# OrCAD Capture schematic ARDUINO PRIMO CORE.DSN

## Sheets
1 Revision: title: Title and Reversion History; note: FM03-AR9331-DogWiFi
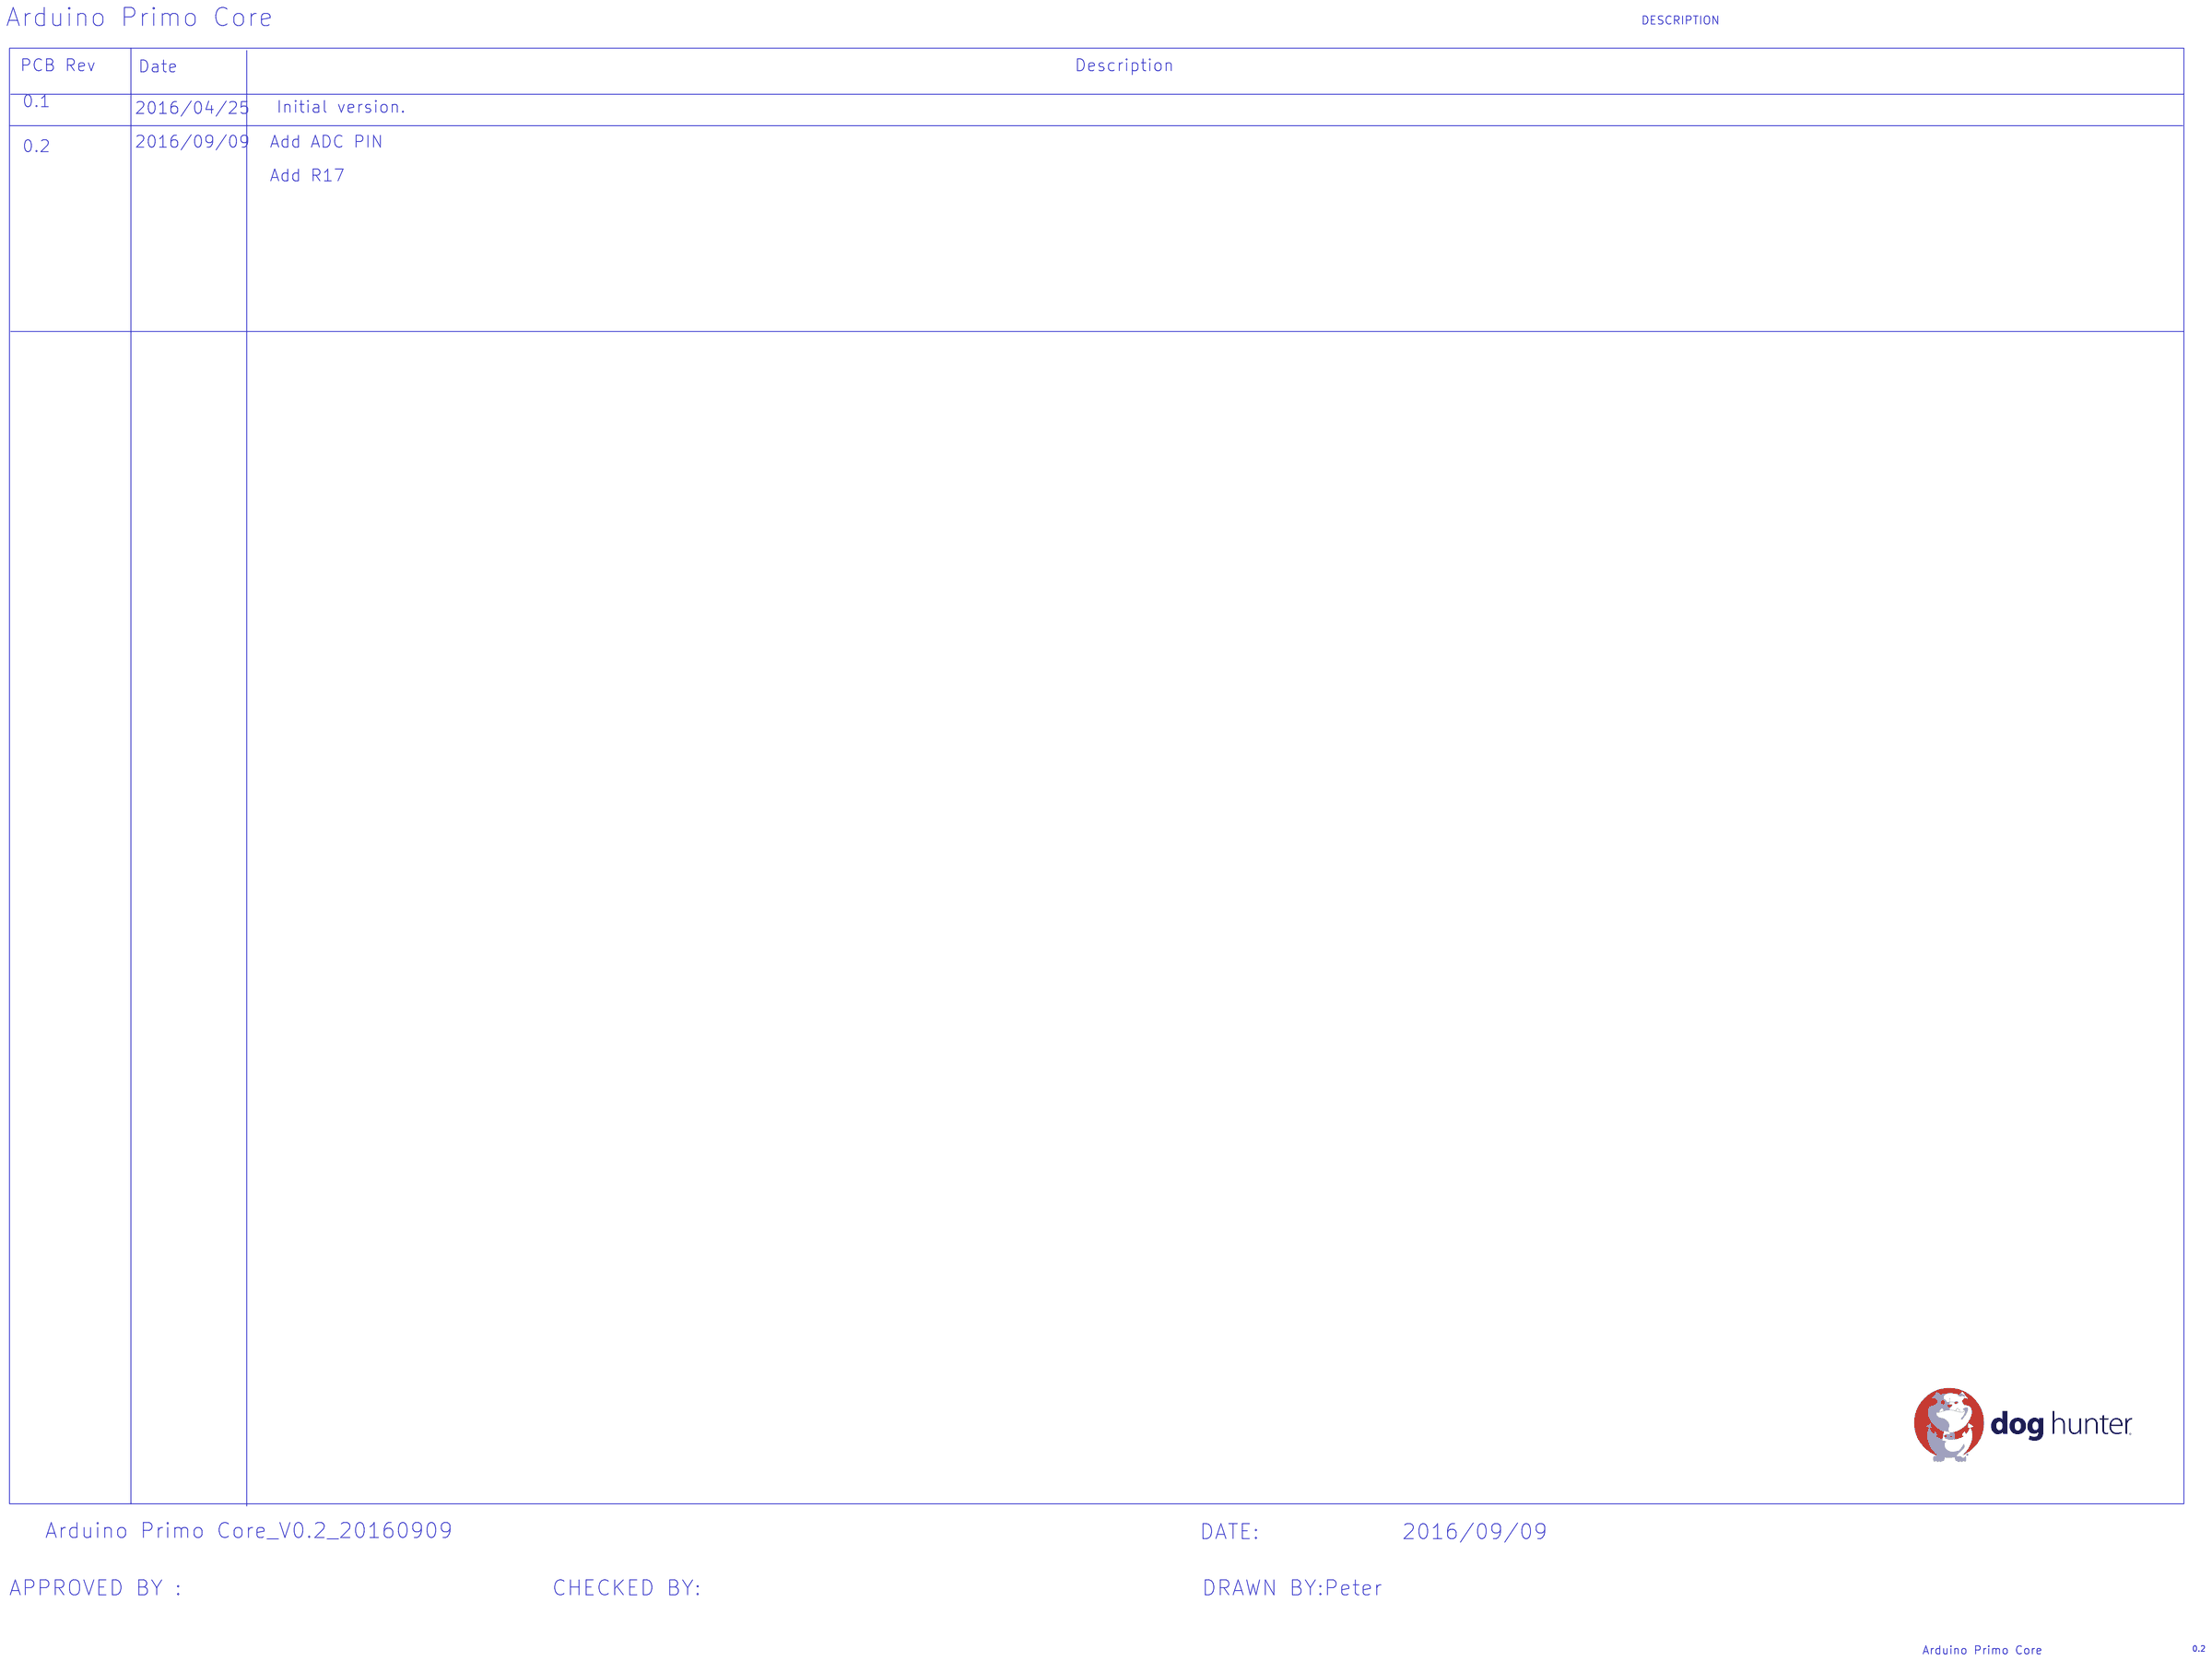
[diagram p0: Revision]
2 Block Diagram: title: Block Diagram; rev: 0.2; company: dog hunter INC; note: Arduino Primo Core; note: Baarerstrasse 14; note: 6300 Zug
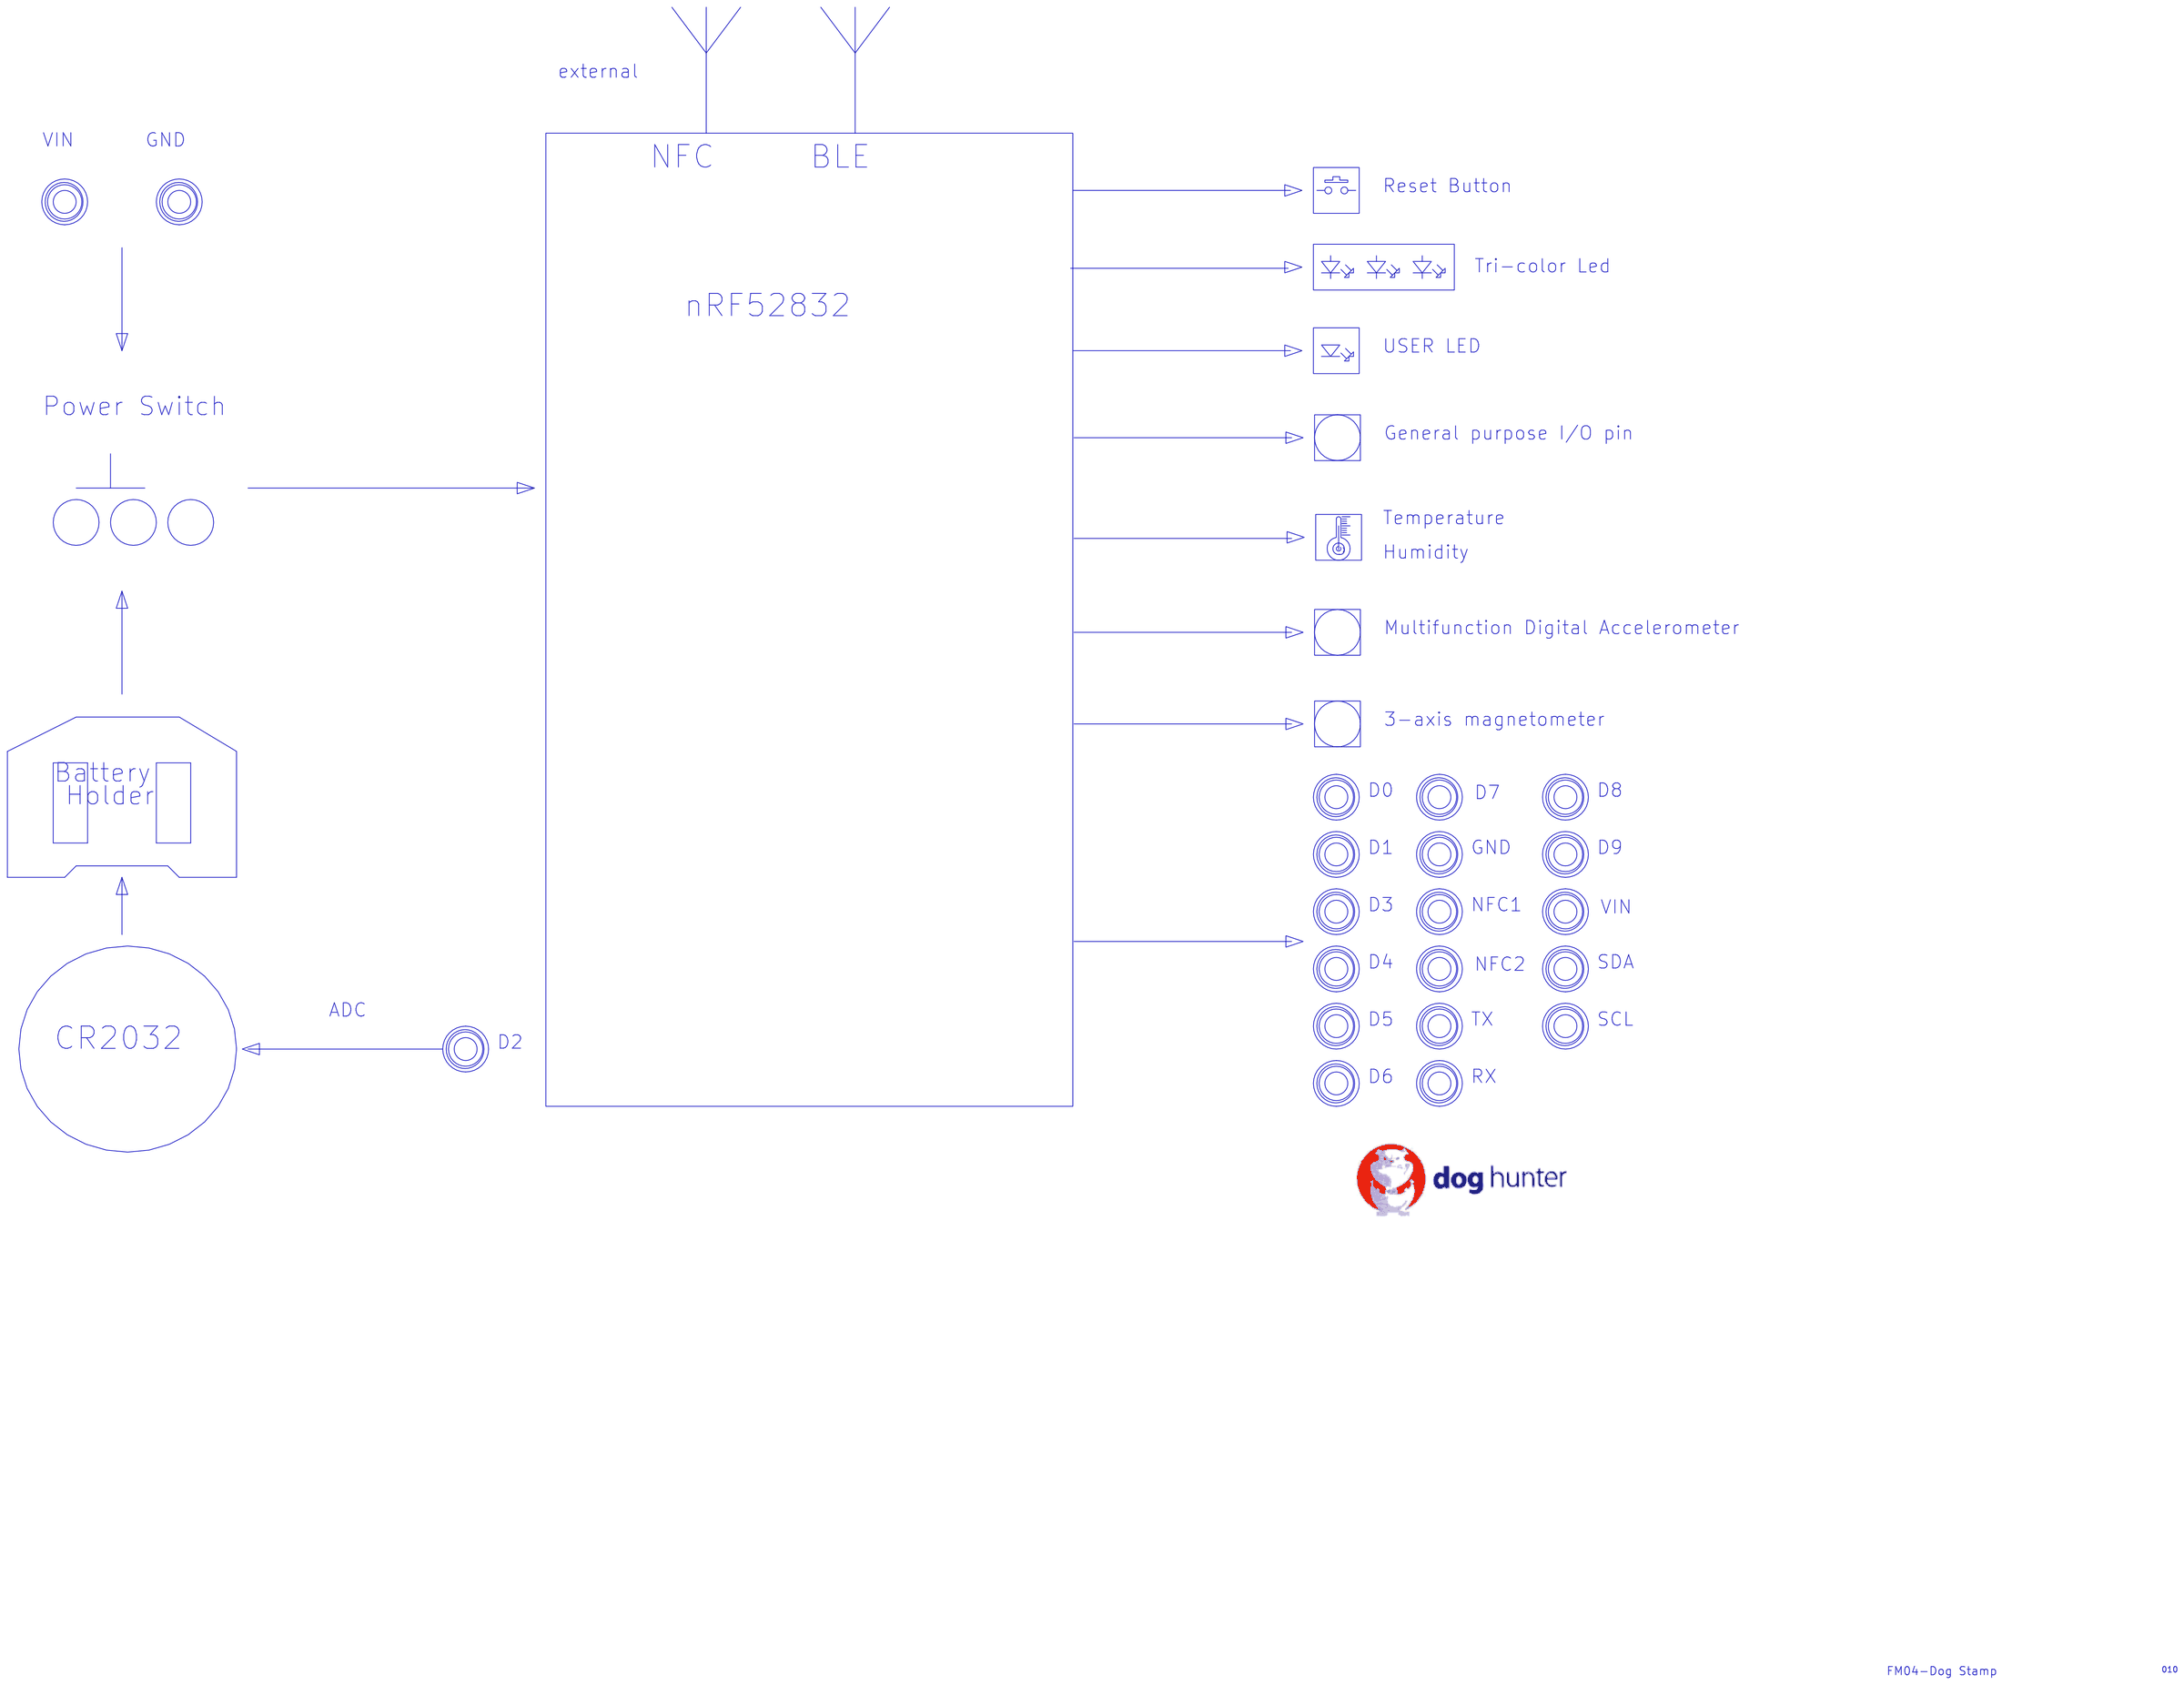
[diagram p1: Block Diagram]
3 POWER Board02: size A3; title: nRF52832; rev: 0.2; company: dog hunter INC; note: ARDUINO Primo Core; note: Baarerstrasse 14; note: 6300 Zug
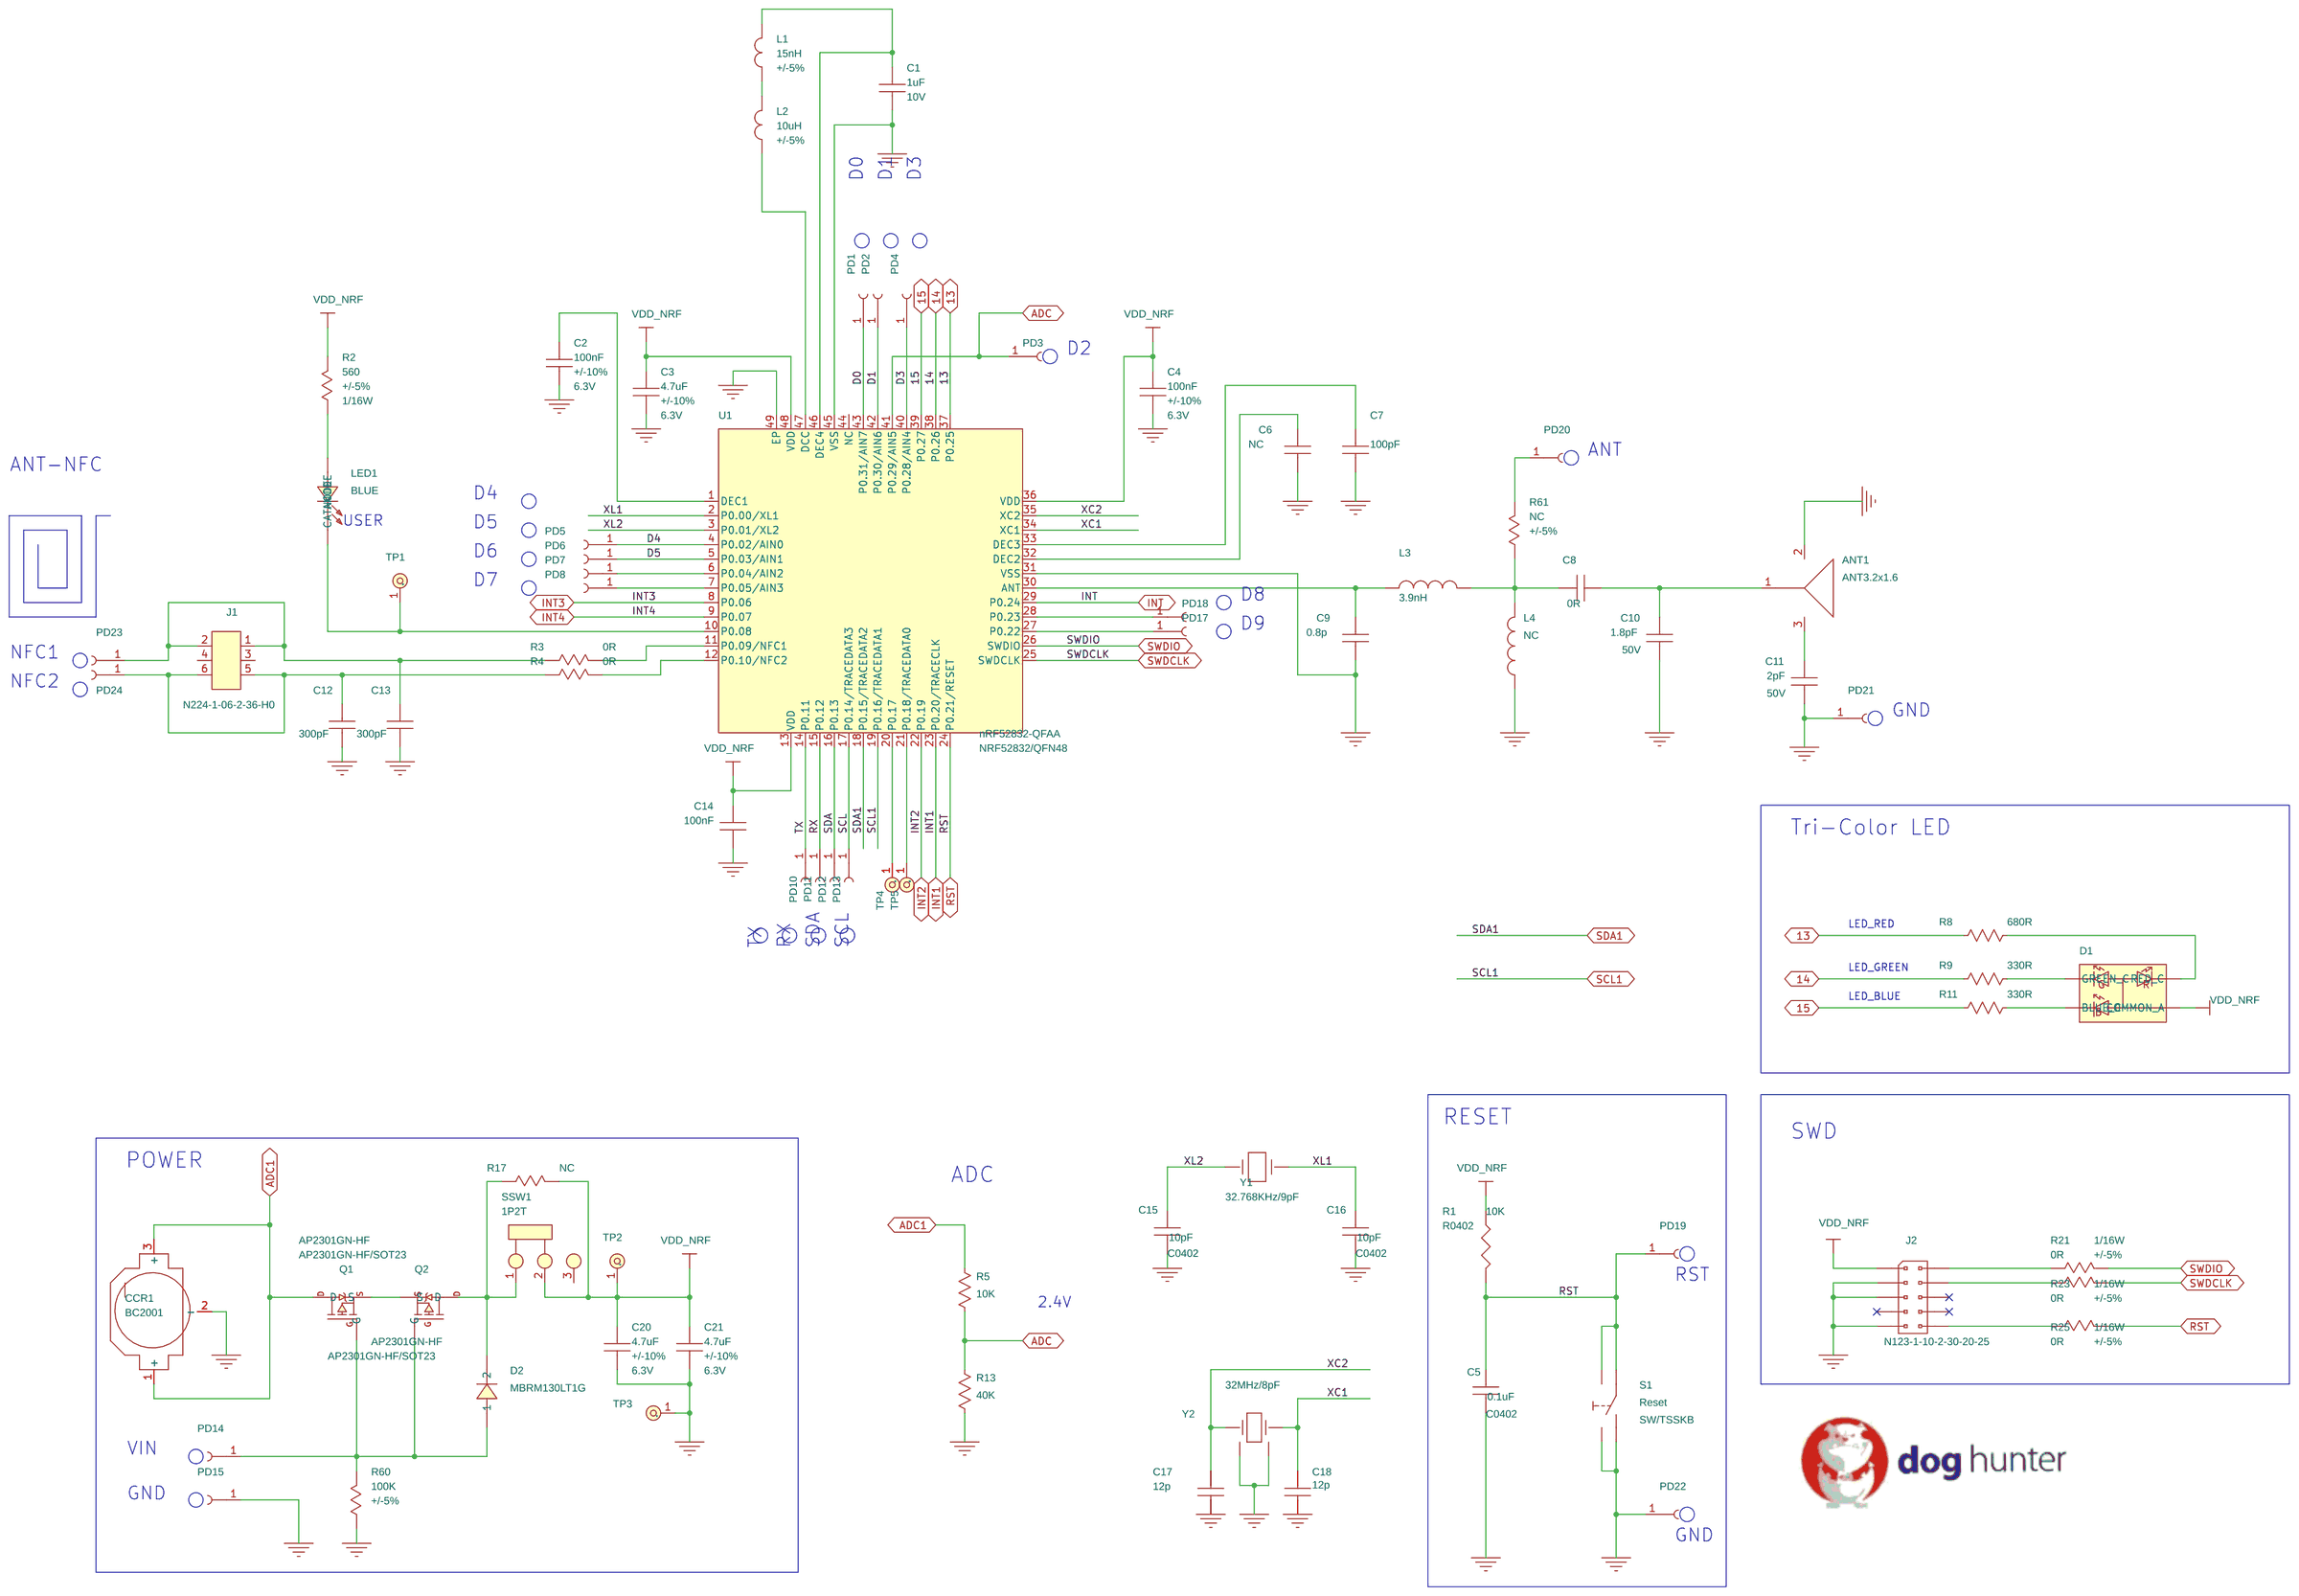
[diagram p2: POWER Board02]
4 SENSOR: size A4; title: nRF52832; rev: 0.2; company: dog hunter INC; note: ARDUINO Primo Core; note: Baarerstrasse 14; note: 6300 Zug
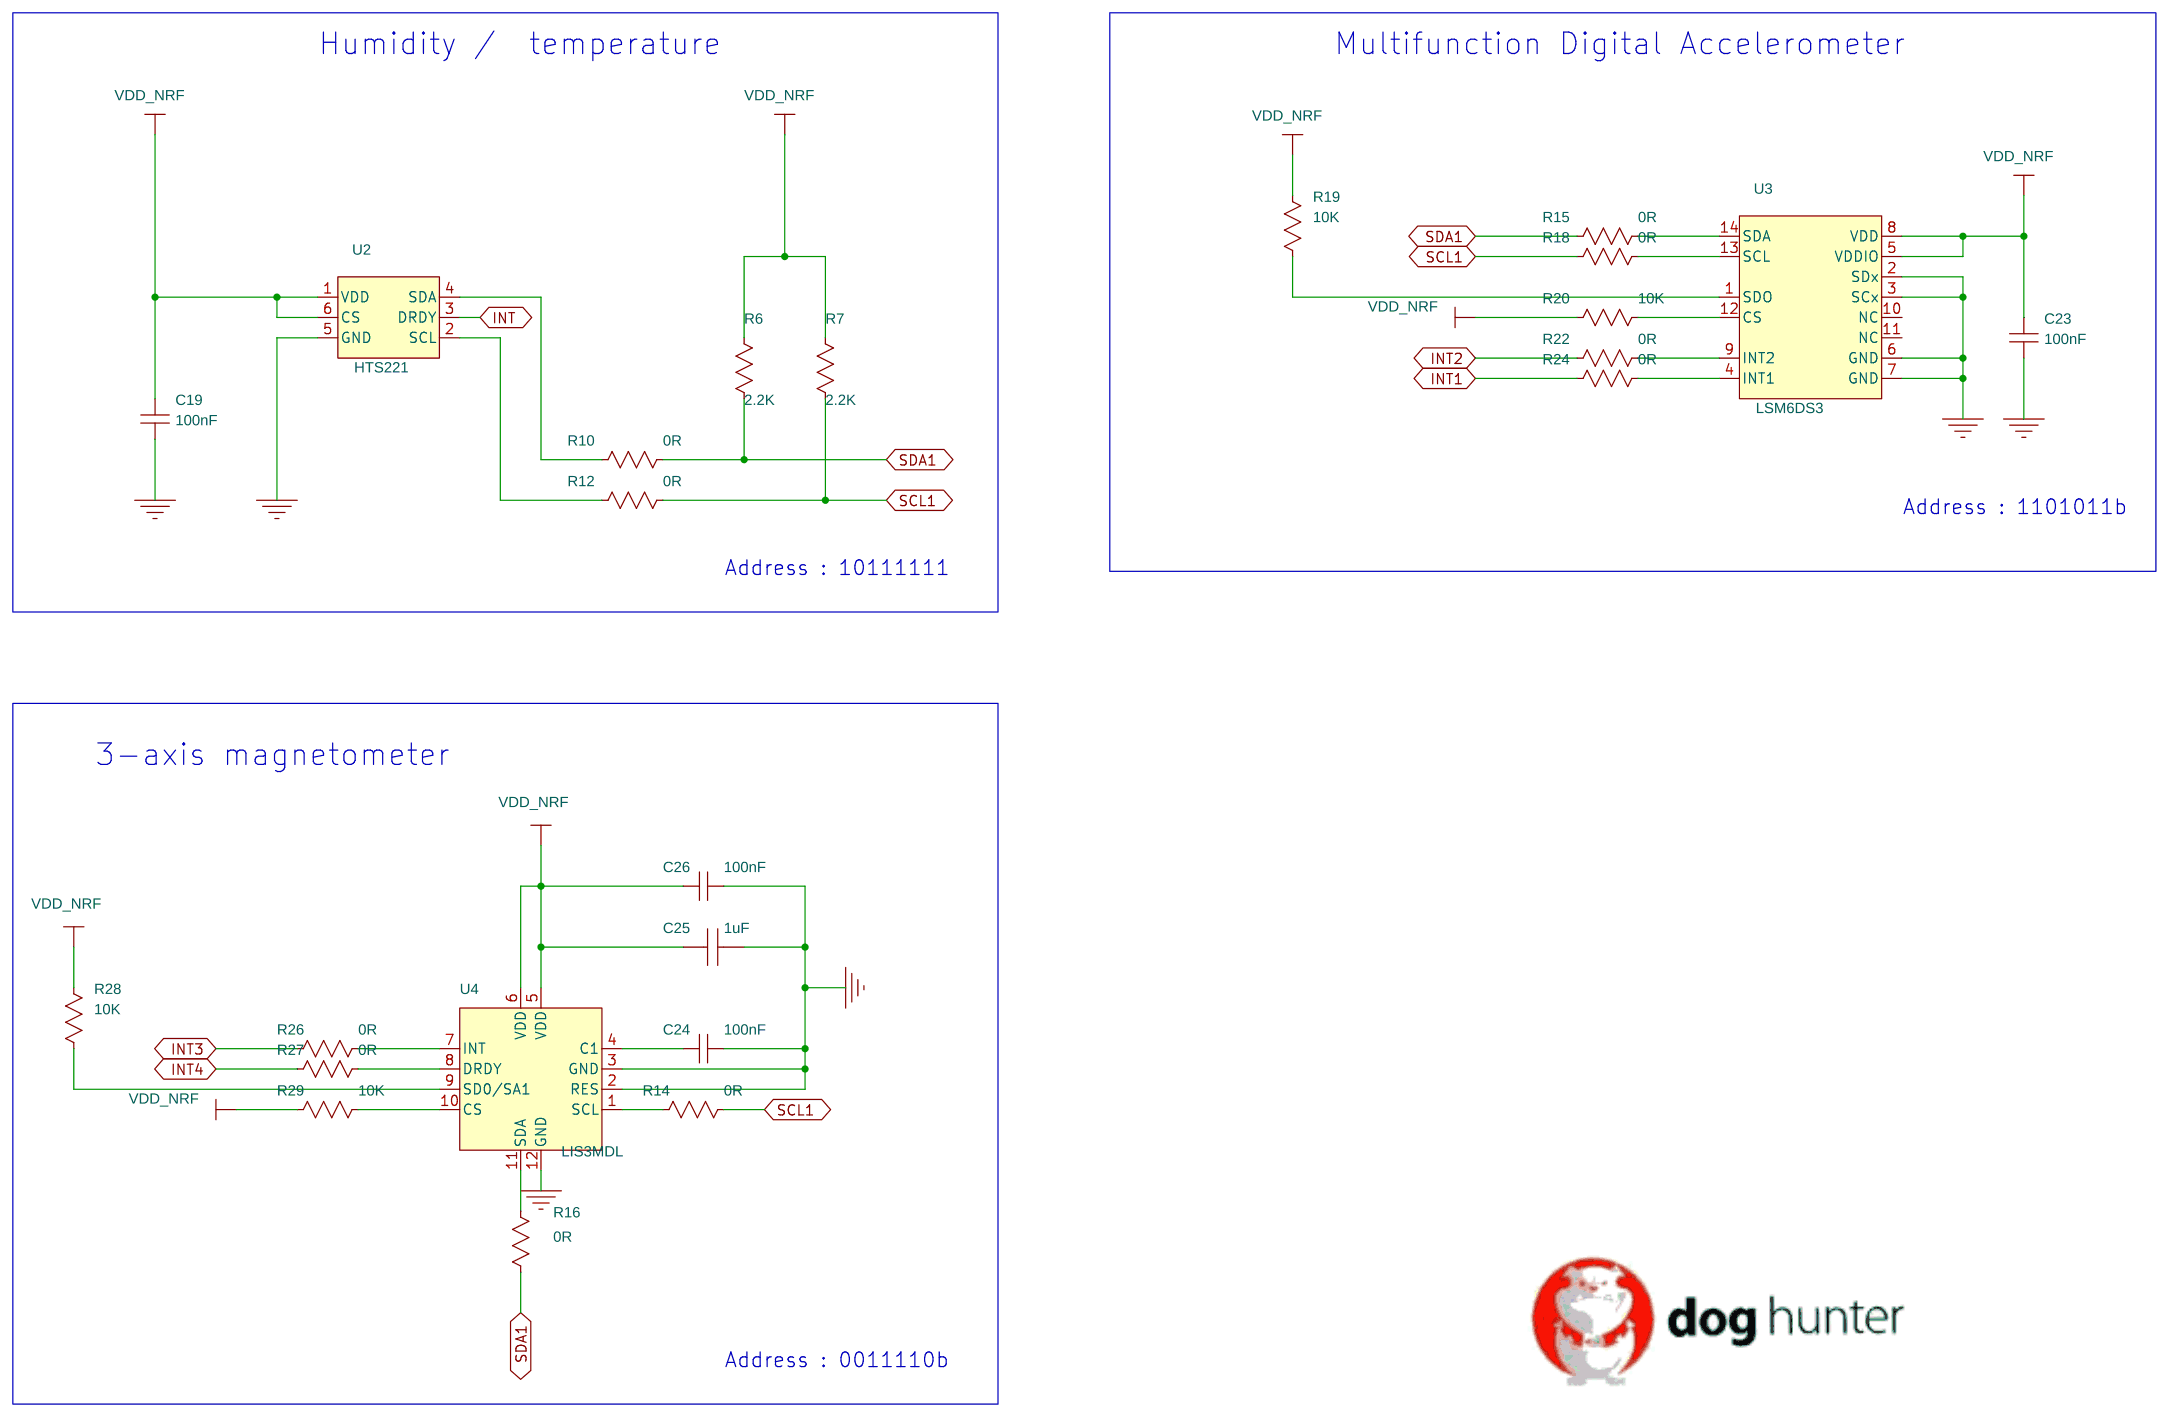
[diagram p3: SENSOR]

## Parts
sheet POWER Board02
ANT1  ANT3.2x1.6  [ANT-3.2X1.6]
C1  1uF  [C0402]
C2  100nF  [C0402]
C3  4.7uF  [C0603]
C4  100nF  [C0402]
C5  0.1uF  [C0402]
C6  NC  [C0402]
C7  100pF  [C0402]
C8  0R  [C0402]
C9  0.8p  [C0402]
C10  1.8pF  [C0402]
C11  2pF  [C0402]
C12  300pF  [C0402]
C13  300pF  [C0402]
C14  100nF  [C0402]
C15  10pF  [C0402]
C16  10pF  [C0402]
C17  12p  [C0402]
C18  12p  [C0402]
C20  4.7uF  [C0603]
C21  4.7uF  [C0603]
CCR1  BC2001  [BC2001]
D1  CLV1A-FKB  [LED/CLV1A-FKB]
D2  MBRM130LT1G  [CASE-457-04]
J1  N224-1-06-2-36-H0  [N224-1-06-2-36-H0]
J2  STRIP_1.27MM_VERT_PTH_5X2  [N123-1-10-2-30-20-25-G1]
L1  15nH  [L0402]
L2  10uH  [L0402]
L3  3.9nH  [L0402]
L4  NC  [L0402]
LED1  BLUE  [LED0603]
PD1  PAD  [PD]
PD2  PAD  [PD]
PD3  PAD  [PD]
PD4  PAD  [PD]
PD5  PAD  [PD]
PD6  PAD  [PD]
PD7  PAD  [PD]
PD8  PAD  [PD]
PD10  PAD  [PD]
PD11  PAD  [PD]
PD12  PAD  [PD]
PD13  PAD  [PD]
PD14  PAD  [PD]
PD15  PAD  [PD]
PD17  PAD  [PD]
PD18  PAD  [PD]
PD19  PAD  [PD]
PD20  PAD  [PD]
PD21  PAD  [PD]
PD22  PAD  [PD]
PD23  PAD  [PD]
PD24  PAD  [PD]
Q1  AP2301GN-HF  [AP2301GN-HF/SOT23]
Q2  AP2301GN-HF  [AP2301GN-HF/SOT23]
R1  10K  [R0402]
R2  560  [R0402]
R3  0R  [R0402]
R4  0R  [R0402]
R5  10K  [R0402]
R8  680R  [R0402]
R9  330R  [R0402]
R11  330R  [R0402]
R13  40K  [R0402]
R17  NC  [R0402]
R21  0R  [R0402]
R23  0R  [R0402]
R25  0R  [R0402]
R60  100K  [R0402]
R61  NC  [R0402]
S1  Reset  [SW/TSSKB]
SSW1  1P2T  [SW/MSK-1290]
TP1  SPI_CMD  [PADA]
TP2  SPI_CMD  [PADA]
TP3  SPI_CMD  [PADA]
TP4  SPI_CMD  [PADA]
TP5  SPI_CMD  [PADA]
U1  nRF52832-QFAA  [NRF52832/QFN48]
Y1  32.768KHz/9pF  [XTAL/S2012R]
Y2  32MHz/8pF  [XTAL/SX2016]
sheet SENSOR
C19  100nF  [C0402]
C23  100nF  [C0402]
C24  100nF  [C0402]
C25  1uF  [C0402]
C26  100nF  [C0402]
R6  2.2K  [R0402]
R7  2.2K  [R0402]
R10  0R  [R0402]
R12  0R  [R0402]
R14  0R  [R0402]
R15  0R  [R0402]
R16  0R  [R0402]
R18  0R  [R0402]
R19  10K  [R0402]
R20  10K  [R0402]
R22  0R  [R0402]
R24  0R  [R0402]
R26  0R  [R0402]
R27  0R  [R0402]
R28  10K  [R0402]
R29  10K  [R0402]
U2  HTS221  [HLGA-6L]
U3  LSM6DS3  [LSM6DS3]
U4  LIS3MDL  [LIS3MDL/VFLGA-2X2X1-12LD]

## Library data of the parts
ANT1 = ANT3.2x1.6
C1 = CAP: ATHEROS KEY: 031-104CK-022; AtherosDescription: CAP,0402,X7R,0.1uF,+/-10%,10V; CISPartType: Capacitor\0402; Tolerance: +/-10%; URL: 0; VendorDescription: equivalent of PHYCOMP / 04022F104M7B20D; VendorName: Yageo; VendorPart1: 662; Voltage: 10V
C2-C4 C20 C21 C25 = CAP: ATHEROS KEY: 032-106CM-002; AtherosDescription: CAP,0603,X5R,10uF,+/-20%,10V; CISPartType: Capacitor\0603; Tolerance: +/-10%; Voltage: 6.3V
C5 C8 = CAP_NP_v2
C6 C7 C9-C14 = CAP: ATHEROS KEY: 031-010CC-000; AtherosDescription: CAP,0402,NPO,1pF,+/-0.25pF,50V; CISPartType: Capacitor\0402; Tolerance: +/-0.25PF; Voltage: 50V
C15 C16 = 27PF_N_0402_5%
C17 C18 = CAP: ATHEROS KEY: 031-8R2CC-000; AtherosDescription: CAP,0402,NPO,8.2pF,+/-0.25pF,50V; CISPartType: Capacitor\0402; Tolerance: +/-0.25PF; Voltage: 50V
CCR1 = CCR-2004_0
D1 = CLV1A_LED_4P: LED RED/GREEN/BLUE PLCC4 SMD; AGILE_PN: 370-76567; CAD_APPROVED: Yes; HEIGHT: 2.1MM; MFG_NAME01: CREE, INC; MFG_PN01: CLV1A-FKB-CJ1M1F1BB7R4S3; Package: PLCC 4; Part Number: CLV1A-FKB-CJ1M1F1BB7R4S3; Part Type: Triple Led; ROHS: Yes
D2 = DIODE_1
J1 = NFC_CON_2
J2 = STRIP_5X2: CONN HEADER 10POS DUAL .050" PTH; DESCR: N123-1-10-2-30-20-25; Part Number: HEADER_1.27MM_VERT_PTH_5X2; Part Type: Berg Unshrouded
L1 = IND: ATHEROS KEY: 071-120LJ-000; AtherosDescription: IND,0402,12nH,+/-5%; CISPartType: Inductor\0402; Tolerance: +/-5%
L2 = IND_1: ATHEROS KEY: 071-120LJ-000; AtherosDescription: IND,0402,12nH,+/-5%; CISPartType: Inductor\0402; Tolerance: +/-5%
L3 L4 = INDUCTOR
LED1 = LED-0603-LTST-C190GKT_0: AtherosDescription: DIO,LED,GREEN CLEAR,0603,SMD; CISPartType: Diodes\LED
PD1-PD8 PD11-PD13 PD17-PD24 = PAD_4
PD10 PD14 PD15 = PAD_5
Q1 Q2 = MOSFET_N_0
R1 = R_v2
R2 R60 R61 = RES: ATHEROS KEY: 051-103RJ-000; AtherosDescription: RES,0402,10K OHMS,+/-5%,1/16W; CISPartType: Resistor\0402; Tolerance: +/-5%; WATTAGE: 1/16W
R3 R4 R17 = RES: ATHEROS KEY: 051-104RF-000; AtherosDescription: RES,0402,100K OHMS,+/-1%,1/16W; CISPartType: Resistor\0402; Tolerance: +/-1%; WATTAGE: 1/16W
R5 R13 = R: RES 10K OHM 1/20W 5% 0201 SMD; Package: 0201; Part Number: RES_10K_OHM_1/20W_5%_0201_SMD; Part type: Thick film; Power: 1/20W; Tolerance: 5%
R8 = R: RES 680 OHM 1/16W 5% 0402 SMD; Package: 0402; Part Number: RES_680_OHM_1/16W_5%_0402_SMD; Part type: Thick film; Power: 1/16W; Tolerance: 5%
R9 R11 = R: RES 330 OHM 1/16W 5% 0402 SMD; Package: 0402; Part Number: RES_330_OHM_1/16W_5%_0402_SMD; Part type: Thick film; Power: 1/16W; Tolerance: 5%
R21 R23 R25 = RES: ATHEROS KEY: 051-102RJ-000; AtherosDescription: RES,0402,1K OHMS,+/-5%,1/16W; CISPartType: Resistor\0402; Tolerance: +/-5%; WATTAGE: 1/16W
S1 = SW_PUSHBUTTON_2
SSW1 = 1P2T
TP1-TP5 = TP
U1 = nRF52832_0
Y1 = CRY_SM_24MHz_4P_0
Y2 = XTAL-TH-HC49-25MHz_3: AtherosDescription: XTAL,HC-49/S,Thru_Hole,25.000MHZ; CISPartType: Crystals
C19 C23 C24 C26 = CAP_NP: CAP CER 0.1UF 16V 10% X7R 0402; Package: 0402; Part Number: CAP_CER_0.1UF_16V_10%_X7R_0402; Part Type: Ceramic; Temp Coeff: X7R; Tolerance: 10%; Voltage: 16V
R6 R7 R10 R12 R14-R16 R18-R20 R22 R24 R26-R29 = R: RES 0.0 OHM 1/16W JUMP 0402 SMD; Package: 0402; Part Number: RES_0.0_OHM_1/16W_JUMP_0402_SMD; Part type: Thick film; Power: 1/16W; Tolerance: NA
U2 = HTS221
U3 = LSM6DSL_0
U4 = LIS3MDL

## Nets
GND: ANT1.2 C1.Pin2 C2.Pin2 C3.Pin2 C4.Pin2 C5.2 C6.2(Pin2) C7.2(Pin2) C9.2(Pin2) C10.2(Pin2) C11.2(Pin2) C12.2(Pin2) C13.2(Pin2) C14.2(Pin2) C15.2 C16.2 C17.2(Pin2) C18.2(Pin2) C19.1 C20.Pin2 C21.Pin2 C23.1 C24.2 C25.Pin2 C26.2 CCR1.2(-) J2.3 J2.5 J2.9 L4.2 PD15.1 PD21.1 PD22.1 R13.1 R60.1(Pin1) S1.3 S1.4 TP3.1(.) U1.31(VSS) U1.45(VSS) U1.49(EP) U2.5(GND) U3.2(SDx) U3.3(SCx) U3.6(GND) U3.7(GND) U4.2(RES) U4.3(GND) U4.12(GND) Y2.2 Y2.4
VDD_nRF: C3.Pin1 C4.Pin1 C14.1(Pin1) C19.2 C20.Pin1 C21.Pin1 C23.2 C25.Pin1 C26.1 D1.2(COMMON_A) J2.1 R1.1 R2.2(Pin2) R6.2 R7.2 R17.2(Pin2) R19.2 R20.1 R28.1 R29.2 SSW1.2 TP2.1(.) U1.13(VDD) U1.36(VDD) U1.48(VDD) U2.1(VDD) U2.6(CS) U3.5(VDDIO) U3.8(VDD) U4.5(VDD) U4.6(VDD)
13: R8.1 U1.37(P0.25)
14: R9.1 U1.38(P0.26)
15: R11.1 U1.39(P0.27)
ADC: PD3.1 R5.1 R13.2 U1.41(P0.29/AIN5)
ADC1: CCR1.1(+) CCR1.3(+) Q1.2(D) R5.2
D0: PD1.1 U1.43(P0.31/AIN7)
D1: PD2.1 U1.42(P0.30/AIN6)
D3: PD4.1 U1.40(P0.28/AIN4)
D4: PD5.1 U1.4(P0.02/AIN0)
D5: PD6.1 U1.5(P0.03/AIN1)
INT: U1.29(P0.24) U2.3(DRDY)
INT1: R24.1 U1.23(P0.20/TRACECLK)
INT2: R22.1 U1.22(P0.19)
INT3: R26.2 U1.8(P0.06)
INT4: R27.2 U1.9(P0.07)
RST: C5.1 PD19.1 R1.2 R25.2(Pin2) S1.1 S1.2 U1.24(P0.21/RESET)
RX: PD11.1 U1.15(P0.12)
SCL: PD13.1 U1.17(P0.14/TRACEDATA3)
SCL1: R7.1 R12.2 R14.1 R18.1 U1.19(P0.16/TRACEDATA1)
SDA: PD12.1 U1.16(P0.13)
SDA1: R6.1 R10.2 R15.1 R16.2 U1.18(P0.15/TRACEDATA2)
SWDCLK: R23.2(Pin2) U1.25(SWDCLK)
SWDIO: R21.2(Pin2) U1.26(SWDIO)
TX: PD10.1 U1.14(P0.11)
XC1: C18.1(Pin1) U1.34(XC1) Y2.3
XC2: C17.1(Pin1) U1.35(XC2) Y2.1
XL1: C16.1 U1.2(P0.00/XL1) Y1.2
XL2: C15.1 U1.3(P0.01/XL2) Y1.1
N31829828: C13.1(Pin1) J1.1 J1.2 PD23.1 R3.1(Pin1)
N31829830: R3.2(Pin2) U1.11(P0.09/NFC1)
N31829836: R4.2(Pin2) U1.12(P0.10/NFC2)
N31829852: C12.1(Pin1) J1.5 J1.6 PD24.1 R4.1(Pin1)
N31830090: C2.Pin1 U1.1(DEC1)
N31830134: C1.Pin1 L1.1 U1.46(DEC4)
N31830136: L1.2 L2.1
N31830138: L2.2 U1.47(DCC)
N31830156: LED1.1(ANODE) R2.1(Pin1)
N31830165: LED1.2(CATHODE) TP1.1(.) U1.10(P0.08)
N31830345: C9.1(Pin1) L3.2 U1.30(ANT)
N31830371: C8.2 L3.1 L4.1 R61.1(Pin1)
N31830373: ANT1.1 C8.1 C10.1(Pin1)
N31830462: C6.1(Pin1) U1.32(DEC2)
N31830464: C7.1(Pin1) U1.33(DEC3)
N31835220: J2.10 R25.1(Pin1)
N31835309: J2.2 R21.1(Pin1)
N31835329: J2.4 R23.1(Pin1)
N31842762: D1.1(RED_C) R8.2
N31842777: D1.4(GREEN_C) R9.2
N31842787: D1.3(BLUE_C) R11.2
N31861196: D2.A(1) PD14.1 Q1.1(G) Q2.1(G) R60.2(Pin2)
N31861434: Q1.3(S) Q2.3(S)
N31862397: D2.C(2) Q2.2(D) R17.1(Pin1) SSW1.1
N31864646: PD20.1 R61.2(Pin2)
N31884176: ANT1.3 C11.1(Pin1)
N31885933: R12.1 U2.2(SCL)
N31886011: R10.1 U2.4(SDA)
N31886509: R20.2 U3.12(CS)
N31886513: R22.2 U3.9(INT2)
N31886517: R24.2 U3.4(INT1)
N31886533: R15.2 U3.14(SDA)
N31886535: R18.2 U3.13(SCL)
N31886957: R16.1 U4.11(SDA)
N31886976: R14.2 U4.1(SCL)
N31887552: C24.1 U4.4(C1)
N31887973: R26.1 U4.7(INT)
N31887976: R27.1 U4.8(DRDY)
N31887982: R29.1 U4.10(CS)
N31891191: PD7.1 U1.6(P0.04/AIN2)
N31891194: PD8.1 U1.7(P0.05/AIN3)
N31895861: R19.1 U3.1(SDO)
N31896072: R28.2 U4.9(SD0/SA1)
N31896543: TP4.1(.) U1.20(P0.17)
N31896546: TP5.1(.) U1.21(P0.18/TRACEDATA0)
N31905219: PD18.1 U1.28(P0.23)
N31905222: PD17.1 U1.27(P0.22)

Not connected (* = marked no-connect by the designer): J1 3 4; J2 6* 7* 8*; SSW1 3; U1 44(NC); U3 10(NC) 11(NC)

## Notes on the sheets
sheet 1
- Arduino Primo Core
- DESCRIPTION
- PCB Rev
- Date
- Description
- 0.1
- 2016/04/25
- Initial version.
- 0.2
- 2016/09/09
- Add ADC PIN
- Add R17
- Arduino Primo Core_V0.2_20160909
- DATE:
- 2016/09/09
- APPROVED BY :
- CHECKED BY:
- DRAWN BY:Peter
- Arduino Primo Core
- 0.2
sheet 2
- external
- VIN
- GND
- NFC
- BLE
- Reset Button
- Tri-color Led
- nRF52832
- USER LED
- Power Switch
- General purpose I/O pin
- Temperature
- Humidity
- Multifunction Digital Accelerometer
- 3-axis magnetometer
- Battery
- D0
- D8
- Holder
- D7
- D1
- GND
- D9
- D3
- NFC1
- VIN
- D4
- NFC2
- SDA
- ADC
- D5
- TX
- SCL
- CR2032
- D2
- D6
- RX
- FM04-Dog Stamp
- 010
sheet 3
- D0
- D1
- D3
- D2
- ANT
- ANT-NFC
- D4
- USER
- D5
- D6
- D7
- D8
- D9
- NFC1
- NFC2
- GND
- Tri-Color LED
- LED_RED
- TX
- RX
- SDA
- SCL
- LED_GREEN
- LED_BLUE
- RESET
- SWD
- POWER
- ADC
- RST
- 2.4V
- VIN
- GND
- GND
sheet 4
- Humidity /  temperature
- Multifunction Digital Accelerometer
- Address : 1101011b
- Address : 10111111
- 3-axis magnetometer
- Address : 0011110b
